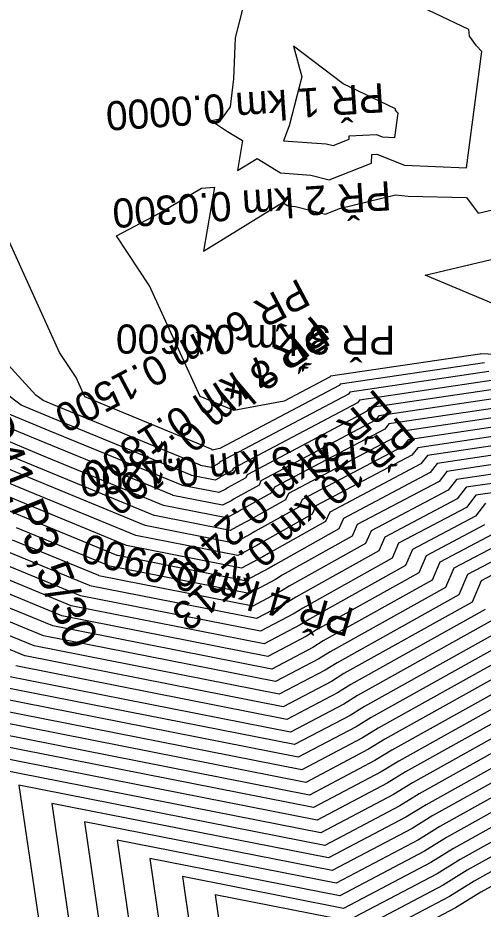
# Model space of a CAD drawing. Extents: x -549394 to -546608, y -1037055 to -1033629.
# Drawn here: x -547337.6 to -547192.8, y -1036070.9 to -1035793.8 of the extents above; entities that cross this region are included whole.
import ezdxf

# ---------------------------------------------------------------- set-up
doc = ezdxf.new("R2010")
doc.units = 0
for name, color, linetype in [('hlavni_vrst', 7, 'Continuous'), ('norm_vrst', 7, 'Continuous'), ('x_popis_pricne_rezy_C41', 7, 'Continuous'), ('x_popis_velky_C41', 7, 'Continuous')]:
    doc.layers.add(name, color=color, linetype=linetype)

msp = doc.modelspace()

# ---------------------------------------------------------------- linework, layer by layer
at = {"layer": 'hlavni_vrst'}
for p, q in [((-547251.82, -1035802.56), (-547249.25, -1035812.17)), ((-547236.37, -1035814.31), (-547251.82, -1035802.56)), ((-547249.25, -1035812.17), (-547253.15, -1035827.42)), ((-547220.11, -1035822.08), (-547236.37, -1035814.31)), ((-547220.26, -1035830.95), (-547219.26, -1035823.48)), ((-547220.05, -1035822.5), (-547220.11, -1035822.08)), ((-547219.61, -1035823.12), (-547220.05, -1035822.5)), ((-547219.26, -1035823.48), (-547219.61, -1035823.12)), ((-547253.15, -1035827.42), (-547254.99, -1035832)), ((-547254.99, -1035832), (-547241.63, -1035832.93)), ((-547239.49, -1035833.48), (-547234.56, -1035831.56)), ((-547234.56, -1035831.56), (-547234.51, -1035830.53)), ((-547234.51, -1035830.53), (-547226.01, -1035830.08)), ((-547226.01, -1035830.08), (-547224.23, -1035830.78)), ((-547224.23, -1035830.78), (-547220.26, -1035830.95)), ((-547241.63, -1035832.93), (-547239.49, -1035833.48)), ((-547332, -1035911.09), (-547360.95, -1035879.77)), ((-547191.02, -1035903.73), (-547234.27, -1035910.17)), ((-547329.73, -1035912.78), (-547332, -1035911.09)), ((-547325.32, -1035914.6), (-547329.73, -1035912.78)), ((-547234.76, -1035910.81), (-547274.88, -1035931.97)), ((-547234.27, -1035910.17), (-547234.76, -1035910.81)), ((-547280.8, -1035932.89), (-547325.32, -1035914.6)), ((-547184.08, -1035917.28), (-547219.2, -1035922.5)), ((-547331.66, -1035933.5), (-547363.96, -1035920.2)), ((-547219.2, -1035922.5), (-547220.63, -1035924.36)), ((-547220.63, -1035924.36), (-547253.44, -1035941.66)), ((-547275, -1035932.24), (-547276.65, -1035933.17)), ((-547274.88, -1035931.97), (-547275, -1035932.24)), ((-547177.14, -1035930.82), (-547204.14, -1035934.84)), ((-547295.17, -1035948.49), (-547331.66, -1035933.5)), ((-547280.76, -1035932.94), (-547280.8, -1035932.89)), ((-547277.43, -1035933.59), (-547280.76, -1035932.94)), ((-547276.81, -1035933.27), (-547277.43, -1035933.59)), ((-547276.65, -1035933.17), (-547276.81, -1035933.27)), ((-547204.14, -1035934.84), (-547206.51, -1035937.92)), ((-547206.51, -1035937.92), (-547231.99, -1035951.36)), ((-547253.44, -1035941.66), (-547254.29, -1035943.62)), ((-547254.29, -1035943.62), (-547265.99, -1035950.15)), ((-547295.14, -1035948.53), (-547295.17, -1035948.49)), ((-547271.55, -1035953.18), (-547295.14, -1035948.53)), ((-547267.14, -1035950.86), (-547271.55, -1035953.18)), ((-547265.99, -1035950.15), (-547267.14, -1035950.86)), ((-547231.99, -1035951.36), (-547233.57, -1035954.99)), ((-547192.38, -1035951.47), (-547210.55, -1035961.05)), ((-547309.54, -1035964.1), (-547338, -1035952.4)), ((-547233.57, -1035954.99), (-547255.34, -1035967.13)), ((-547210.55, -1035961.05), (-547212.86, -1035966.36)), ((-547309.51, -1035964.13), (-547309.54, -1035964.1)), ((-547265.67, -1035972.76), (-547309.51, -1035964.13)), ((-547255.34, -1035967.13), (-547257.47, -1035968.45)), ((-547212.86, -1035966.36), (-547244.68, -1035984.12)), ((-547257.47, -1035968.45), (-547265.67, -1035972.76)), ((-547323.91, -1035979.7), (-547344.34, -1035971.31)), ((-547192.14, -1035977.73), (-547234.02, -1036001.1)), ((-547323.89, -1035979.72), (-547323.91, -1035979.7)), ((-547259.78, -1035992.35), (-547323.89, -1035979.72)), ((-547244.68, -1035984.12), (-547247.8, -1035986.04)), ((-547247.8, -1035986.04), (-547259.78, -1035992.35)), ((-547171.43, -1035989.1), (-547223.36, -1036018.08)), ((-547253.9, -1036011.93), (-547338.27, -1035995.32)), ((-547234.02, -1036001.1), (-547238.12, -1036003.63)), ((-547238.12, -1036003.63), (-547253.9, -1036011.93)), ((-547161.94, -1036006.74), (-547212.7, -1036035.07)), ((-547248.01, -1036031.52), (-547352.65, -1036010.92)), ((-547223.36, -1036018.08), (-547228.45, -1036021.22)), ((-547228.45, -1036021.22), (-547248.01, -1036031.52)), ((-547337.27, -1036032.37), (-547329.59, -1036084.85)), ((-547242.13, -1036051.11), (-547337.27, -1036032.37)), ((-547212.7, -1036035.07), (-547218.78, -1036038.81)), ((-547218.78, -1036038.81), (-547242.13, -1036051.11)), ((-547177.7, -1036038.46), (-547202.05, -1036052.05)), ((-547202.05, -1036052.05), (-547209.1, -1036056.41)), ((-547209.1, -1036056.41), (-547236.25, -1036070.69)), ((-547286.38, -1036060.82), (-547282.33, -1036088.47)), ((-547236.25, -1036070.69), (-547286.38, -1036060.82))]:
    msp.add_line(p, q, dxfattribs=at)
at = {"layer": 'norm_vrst'}
for p, q in [((-547197.3, -1035797.44), (-547264.33, -1035765.41)), ((-547266.72, -1035787.33), (-547269.97, -1035799.98)), ((-547197.02, -1035799.47), (-547197.3, -1035797.44)), ((-547269.97, -1035799.98), (-547270.5, -1035812.79)), ((-547194.88, -1035802.45), (-547197.02, -1035799.47)), ((-547198.02, -1035840.41), (-547193.19, -1035804.21)), ((-547193.19, -1035804.21), (-547194.88, -1035802.45)), ((-547270.5, -1035812.79), (-547271.59, -1035821.51)), ((-547271.59, -1035821.51), (-547274.2, -1035825.16)), ((-547274.2, -1035825.16), (-547277.37, -1035825.83)), ((-547277.37, -1035825.83), (-547272.34, -1035829.09)), ((-547272.34, -1035829.09), (-547267.66, -1035831.93)), ((-547267.66, -1035831.93), (-547269.28, -1035841.28)), ((-547269.28, -1035841.28), (-547263.18, -1035837.53)), ((-547263.18, -1035837.53), (-547255.86, -1035842.02)), ((-547227.55, -1035839.03), (-547227.44, -1035836.28)), ((-547227.44, -1035836.28), (-547225.9, -1035836.2)), ((-547225.9, -1035836.2), (-547217.26, -1035839.59)), ((-547240.7, -1035844.14), (-547227.55, -1035839.03)), ((-547217.26, -1035839.59), (-547198.02, -1035840.41)), ((-547255.86, -1035842.02), (-547246.41, -1035842.68)), ((-547246.41, -1035842.68), (-547240.7, -1035844.14)), ((-547293.7, -1035854.68), (-547280.51, -1035846.71)), ((-547280.51, -1035846.71), (-547276.4, -1035846.42)), ((-547276.4, -1035846.42), (-547279.84, -1035866.32)), ((-547237.47, -1035853.07), (-547220.1, -1035848.82)), ((-547220.1, -1035848.82), (-547216.13, -1035849.24)), ((-547279.84, -1035866.32), (-547255.25, -1035851.18)), ((-547255.25, -1035851.18), (-547253.48, -1035852.27)), ((-547216.13, -1035849.24), (-547198, -1035849.68)), ((-547198, -1035849.68), (-547194.35, -1035854.53)), ((-547194.35, -1035854.53), (-547180.63, -1035851.28)), ((-547306.97, -1035861.55), (-547293.7, -1035854.68)), ((-547253.48, -1035852.27), (-547251.19, -1035852.43)), ((-547251.19, -1035852.43), (-547241.91, -1035854.8)), ((-547241.91, -1035854.8), (-547237.47, -1035853.07)), ((-547324.65, -1035897.88), (-547341.16, -1035861.46)), ((-547296.68, -1035877.13), (-547306.97, -1035861.55)), ((-547210.83, -1035873.81), (-547170.49, -1035864.25)), ((-547183, -1035885.49), (-547210.83, -1035873.81)), ((-547280.88, -1035911.53), (-547296.68, -1035877.13)), ((-547319.52, -1035905.63), (-547324.65, -1035897.88)), ((-547193.8, -1035898.32), (-547240.29, -1035905.23)), ((-547193.61, -1035898.22), (-547193.8, -1035898.32)), ((-547158.47, -1035899.73), (-547193.61, -1035898.22)), ((-547192.41, -1035901.02), (-547237.28, -1035907.7)), ((-547316.78, -1035911.6), (-547319.52, -1035905.63)), ((-547240.41, -1035905.39), (-547254.79, -1035912.97)), ((-547240.29, -1035905.23), (-547240.41, -1035905.39)), ((-547189.63, -1035906.44), (-547231.25, -1035912.63)), ((-547237.58, -1035908.1), (-547274.8, -1035927.72)), ((-547237.28, -1035907.7), (-547237.58, -1035908.1)), ((-547188.25, -1035909.15), (-547228.24, -1035915.1)), ((-547336.57, -1035914.27), (-547341.71, -1035910.43)), ((-547277.18, -1035928.05), (-547316.78, -1035911.6)), ((-547270.39, -1035915.88), (-547280.88, -1035911.53)), ((-547231.25, -1035912.63), (-547231.93, -1035913.52)), ((-547186.86, -1035911.86), (-547225.23, -1035917.57)), ((-547326.59, -1035918.38), (-547336.57, -1035914.27)), ((-547231.93, -1035913.52), (-547270.59, -1035933.91)), ((-547254.79, -1035912.97), (-547270.39, -1035915.91)), ((-547228.24, -1035915.1), (-547229.11, -1035916.23)), ((-547185.47, -1035914.57), (-547222.21, -1035920.04)), ((-547329.13, -1035925.94), (-547350.26, -1035917.23)), ((-547327.86, -1035922.16), (-547343.42, -1035915.75)), ((-547283.67, -1035936.01), (-547326.59, -1035918.38)), ((-547270.39, -1035915.91), (-547270.39, -1035915.88)), ((-547229.11, -1035916.23), (-547266.3, -1035935.85)), ((-547225.23, -1035917.57), (-547226.28, -1035918.94)), ((-547330.39, -1035929.72), (-547357.11, -1035918.72)), ((-547226.28, -1035918.94), (-547262.02, -1035937.79)), ((-547222.21, -1035920.04), (-547223.46, -1035921.65)), ((-547182.7, -1035919.99), (-547216.19, -1035924.97)), ((-547334.2, -1035941.06), (-547377.65, -1035923.17)), ((-547332.93, -1035937.28), (-547370.8, -1035921.69)), ((-547286.55, -1035939.13), (-547327.86, -1035922.16)), ((-547223.46, -1035921.65), (-547257.73, -1035939.72)), ((-547181.31, -1035922.69), (-547213.17, -1035927.44)), ((-547336.73, -1035948.62), (-547391.34, -1035926.14)), ((-547335.47, -1035944.84), (-547384.49, -1035924.65)), ((-547289.42, -1035942.25), (-547329.13, -1035925.94)), ((-547216.19, -1035924.97), (-547217.81, -1035927.07)), ((-547179.92, -1035925.4), (-547210.16, -1035929.9)), ((-547274.8, -1035927.72), (-547277.18, -1035928.17)), ((-547277.18, -1035928.17), (-547277.18, -1035928.05)), ((-547217.81, -1035927.07), (-547249.15, -1035943.6)), ((-547213.17, -1035927.44), (-547214.98, -1035929.78)), ((-547178.53, -1035928.11), (-547207.15, -1035932.37)), ((-547292.29, -1035945.37), (-547330.39, -1035929.72)), ((-547214.98, -1035929.78), (-547244.86, -1035945.54)), ((-547210.16, -1035929.9), (-547212.16, -1035932.49)), ((-547270.86, -1035934.52), (-547274.52, -1035936.56)), ((-547270.59, -1035933.91), (-547270.86, -1035934.52)), ((-547212.16, -1035932.49), (-547240.57, -1035947.48)), ((-547207.15, -1035932.37), (-547209.33, -1035935.21)), ((-547175.76, -1035933.53), (-547201.12, -1035937.3)), ((-547298.04, -1035951.61), (-547332.93, -1035937.28)), ((-547283.63, -1035936.06), (-547283.67, -1035936.01)), ((-547276.26, -1035937.51), (-547283.63, -1035936.06)), ((-547274.88, -1035936.78), (-547276.26, -1035937.51)), ((-547274.52, -1035936.56), (-547274.88, -1035936.78)), ((-547266.72, -1035936.79), (-547272.39, -1035939.96)), ((-547266.3, -1035935.85), (-547266.72, -1035936.79)), ((-547262.02, -1035937.79), (-547262.57, -1035939.07)), ((-547209.33, -1035935.21), (-547236.28, -1035949.42)), ((-547201.12, -1035937.3), (-547203.68, -1035940.63)), ((-547174.37, -1035936.24), (-547198.11, -1035939.77)), ((-547286.51, -1035939.18), (-547286.55, -1035939.13)), ((-547275.08, -1035941.43), (-547286.51, -1035939.18)), ((-547272.94, -1035940.3), (-547275.08, -1035941.43)), ((-547272.39, -1035939.96), (-547272.94, -1035940.3)), ((-547262.57, -1035939.07), (-547270.26, -1035943.36)), ((-547257.73, -1035939.72), (-547258.43, -1035941.34)), ((-547198.11, -1035939.77), (-547200.86, -1035943.34)), ((-547172.98, -1035938.95), (-547195.1, -1035942.24)), ((-547300.92, -1035954.73), (-547334.2, -1035941.06)), ((-547289.38, -1035942.3), (-547289.42, -1035942.25)), ((-547273.9, -1035945.34), (-547289.38, -1035942.3)), ((-547270.26, -1035943.36), (-547271.01, -1035943.82)), ((-547258.43, -1035941.34), (-547268.13, -1035946.75)), ((-547203.68, -1035940.63), (-547227.7, -1035953.3)), ((-547200.86, -1035943.34), (-547223.41, -1035955.23)), ((-547195.1, -1035942.24), (-547198.03, -1035946.05)), ((-547303.79, -1035957.86), (-547335.47, -1035944.84)), ((-547292.26, -1035945.41), (-547292.29, -1035945.37)), ((-547272.73, -1035949.26), (-547292.26, -1035945.41)), ((-547271.01, -1035943.82), (-547273.9, -1035945.34)), ((-547250.14, -1035945.89), (-547263.86, -1035953.55)), ((-547249.15, -1035943.6), (-547250.14, -1035945.89)), ((-547244.86, -1035945.54), (-547246, -1035948.16)), ((-547198.03, -1035946.05), (-547219.13, -1035957.17)), ((-547192.08, -1035944.7), (-547195.21, -1035948.76)), ((-547306.67, -1035960.98), (-547336.73, -1035948.62)), ((-547269.08, -1035947.34), (-547272.73, -1035949.26)), ((-547268.13, -1035946.75), (-547269.08, -1035947.34)), ((-547246, -1035948.16), (-547261.73, -1035956.94)), ((-547240.57, -1035947.48), (-547241.86, -1035950.44)), ((-547195.21, -1035948.76), (-547214.84, -1035959.11)), ((-547298.01, -1035951.65), (-547298.04, -1035951.61)), ((-547270.37, -1035957.09), (-547298.01, -1035951.65)), ((-547241.86, -1035950.44), (-547259.6, -1035960.34)), ((-547236.28, -1035949.42), (-547237.71, -1035952.71)), ((-547265.21, -1035954.37), (-547270.37, -1035957.09)), ((-547263.86, -1035953.55), (-547265.21, -1035954.37)), ((-547237.71, -1035952.71), (-547257.47, -1035963.74)), ((-547227.7, -1035953.3), (-547229.43, -1035957.26)), ((-547189.56, -1035954.18), (-547206.26, -1035962.99)), ((-547312.41, -1035967.22), (-547339.27, -1035956.19)), ((-547300.89, -1035954.77), (-547300.92, -1035954.73)), ((-547269.2, -1035961.01), (-547300.89, -1035954.77)), ((-547261.73, -1035956.94), (-547263.27, -1035957.89)), ((-547223.41, -1035955.23), (-547225.29, -1035959.54)), ((-547219.13, -1035957.17), (-547221.14, -1035961.81)), ((-547186.73, -1035956.89), (-547201.97, -1035964.93)), ((-547315.29, -1035970.34), (-547340.54, -1035959.97)), ((-547303.76, -1035957.89), (-547303.79, -1035957.86)), ((-547268.02, -1035964.93), (-547303.76, -1035957.89)), ((-547263.27, -1035957.89), (-547269.2, -1035961.01)), ((-547229.43, -1035957.26), (-547253.2, -1035970.53)), ((-547225.29, -1035959.54), (-547251.07, -1035973.93)), ((-547214.84, -1035959.11), (-547217, -1035964.08)), ((-547183.91, -1035959.6), (-547197.68, -1035966.87)), ((-547306.64, -1035961.01), (-547306.67, -1035960.98)), ((-547266.84, -1035968.85), (-547306.64, -1035961.01)), ((-547261.34, -1035961.41), (-547268.02, -1035964.93)), ((-547259.6, -1035960.34), (-547261.34, -1035961.41)), ((-547221.14, -1035961.81), (-547248.94, -1035977.32)), ((-547181.08, -1035962.31), (-547193.39, -1035968.81)), ((-547318.16, -1035973.46), (-547341.81, -1035963.75)), ((-547259.4, -1035964.93), (-547266.84, -1035968.85)), ((-547257.47, -1035963.74), (-547259.4, -1035964.93)), ((-547217, -1035964.08), (-547246.81, -1035980.72)), ((-547206.26, -1035962.99), (-547208.71, -1035968.63)), ((-547201.97, -1035964.93), (-547204.57, -1035970.91)), ((-547321.04, -1035976.58), (-547343.07, -1035967.53)), ((-547312.39, -1035967.25), (-547312.41, -1035967.22)), ((-547264.49, -1035976.68), (-547312.39, -1035967.25)), ((-547197.68, -1035966.87), (-547200.43, -1035973.18)), ((-547315.27, -1035970.37), (-547315.29, -1035970.34)), ((-547263.31, -1035980.6), (-547315.27, -1035970.37)), ((-547253.2, -1035970.53), (-547255.53, -1035971.97)), ((-547208.71, -1035968.63), (-547242.55, -1035987.51)), ((-547204.57, -1035970.91), (-547240.42, -1035990.91)), ((-547193.39, -1035968.81), (-547196.28, -1035975.46)), ((-547318.14, -1035973.49), (-547318.16, -1035973.46)), ((-547262.14, -1035984.51), (-547318.14, -1035973.49)), ((-547255.53, -1035971.97), (-547264.49, -1035976.68)), ((-547200.43, -1035973.18), (-547238.28, -1035994.31)), ((-547326.78, -1035982.82), (-547345.61, -1035975.09)), ((-547321.02, -1035976.61), (-547321.04, -1035976.58)), ((-547260.96, -1035988.43), (-547321.02, -1035976.61)), ((-547253.6, -1035975.48), (-547263.31, -1035980.6)), ((-547251.07, -1035973.93), (-547253.6, -1035975.48)), ((-547196.28, -1035975.46), (-547236.15, -1035997.7)), ((-547329.66, -1035985.94), (-547346.88, -1035978.87)), ((-547251.66, -1035979), (-547262.14, -1035984.51)), ((-547248.94, -1035977.32), (-547251.66, -1035979)), ((-547246.81, -1035980.72), (-547249.73, -1035982.52)), ((-547188, -1035980), (-547231.89, -1036004.5)), ((-547332.53, -1035989.06), (-547348.15, -1035982.65)), ((-547326.77, -1035982.84), (-547326.78, -1035982.82)), ((-547258.61, -1035996.27), (-547326.77, -1035982.84)), ((-547249.73, -1035982.52), (-547260.96, -1035988.43)), ((-547183.85, -1035982.28), (-547229.76, -1036007.89)), ((-547179.71, -1035984.55), (-547227.63, -1036011.29)), ((-547335.41, -1035992.19), (-547349.41, -1035986.43)), ((-547329.64, -1035985.96), (-547329.66, -1035985.94)), ((-547257.43, -1036000.18), (-547329.64, -1035985.96)), ((-547242.55, -1035987.51), (-547245.86, -1035989.56)), ((-547175.57, -1035986.83), (-547225.49, -1036014.69)), ((-547332.52, -1035989.08), (-547332.53, -1035989.06)), ((-547256.25, -1036004.1), (-547332.52, -1035989.08)), ((-547245.86, -1035989.56), (-547258.61, -1035996.27)), ((-547335.39, -1035992.2), (-547335.41, -1035992.19)), ((-547255.07, -1036008.02), (-547335.39, -1035992.2)), ((-547243.93, -1035993.08), (-547257.43, -1036000.18)), ((-547240.42, -1035990.91), (-547243.93, -1035993.08)), ((-547167.28, -1035991.38), (-547221.23, -1036021.48)), ((-547238.28, -1035994.31), (-547241.99, -1035996.59)), ((-547163.14, -1035993.65), (-547219.1, -1036024.88)), ((-547159, -1035995.92), (-547216.97, -1036028.27)), ((-547252.72, -1036015.85), (-547341.15, -1035998.44)), ((-547241.99, -1035996.59), (-547256.25, -1036004.1)), ((-547236.15, -1035997.7), (-547240.06, -1036000.11)), ((-547251.54, -1036019.77), (-547344.02, -1036001.56)), ((-547240.06, -1036000.11), (-547255.07, -1036008.02)), ((-547158.79, -1036000.4), (-547214.84, -1036031.67)), ((-547250.37, -1036023.69), (-547346.9, -1036004.68)), ((-547231.89, -1036004.5), (-547236.19, -1036007.15)), ((-547249.19, -1036027.6), (-547349.77, -1036007.8)), ((-547236.19, -1036007.15), (-547252.72, -1036015.85)), ((-547229.76, -1036007.89), (-547234.25, -1036010.67)), ((-547234.25, -1036010.67), (-547251.54, -1036019.77)), ((-547227.63, -1036011.29), (-547232.32, -1036014.19)), ((-547246.84, -1036035.44), (-547355.52, -1036014.04)), ((-547232.32, -1036014.19), (-547250.37, -1036023.69)), ((-547225.49, -1036014.69), (-547230.38, -1036017.7)), ((-547165.09, -1036013.08), (-547210.57, -1036038.46)), ((-547245.66, -1036039.35), (-547358.4, -1036017.15)), ((-547230.38, -1036017.7), (-547249.19, -1036027.6)), ((-547168.24, -1036019.43), (-547208.44, -1036041.86)), ((-547244.48, -1036043.27), (-547357.62, -1036020.99)), ((-547221.23, -1036021.48), (-547226.52, -1036024.74)), ((-547226.52, -1036024.74), (-547246.84, -1036035.44)), ((-547219.1, -1036024.88), (-547224.58, -1036028.26)), ((-547171.39, -1036025.77), (-547206.31, -1036045.26)), ((-547243.31, -1036047.19), (-547347.44, -1036026.68)), ((-547224.58, -1036028.26), (-547245.66, -1036039.35)), ((-547216.97, -1036028.27), (-547222.65, -1036031.78)), ((-547222.65, -1036031.78), (-547244.48, -1036043.27)), ((-547214.84, -1036031.67), (-547220.71, -1036035.3)), ((-547174.54, -1036032.12), (-547204.18, -1036048.65)), ((-547220.71, -1036035.3), (-547243.31, -1036047.19)), ((-547327.09, -1036038.06), (-547320.14, -1036085.57)), ((-547240.95, -1036055.02), (-547327.09, -1036038.06)), ((-547210.57, -1036038.46), (-547216.84, -1036042.33)), ((-547216.84, -1036042.33), (-547240.95, -1036055.02)), ((-547208.44, -1036041.86), (-547214.91, -1036045.85)), ((-547316.91, -1036043.75), (-547310.69, -1036086.3)), ((-547239.78, -1036058.94), (-547316.91, -1036043.75)), ((-547214.91, -1036045.85), (-547239.78, -1036058.94)), ((-547206.31, -1036045.26), (-547212.97, -1036049.37)), ((-547180.85, -1036044.81), (-547199.92, -1036055.45)), ((-547204.18, -1036048.65), (-547211.04, -1036052.89)), ((-547306.73, -1036049.44), (-547301.23, -1036087.02)), ((-547238.6, -1036062.86), (-547306.73, -1036049.44)), ((-547212.97, -1036049.37), (-547238.6, -1036062.86)), ((-547184, -1036051.15), (-547197.78, -1036058.84)), ((-547211.04, -1036052.89), (-547237.42, -1036066.77)), ((-547296.56, -1036055.13), (-547291.78, -1036087.75)), ((-547237.42, -1036066.77), (-547296.56, -1036055.13)), ((-547199.92, -1036055.45), (-547207.17, -1036059.92)), ((-547197.78, -1036058.84), (-547205.23, -1036063.44)), ((-547187.15, -1036057.5), (-547195.65, -1036062.24)), ((-547207.17, -1036059.92), (-547235.07, -1036074.61)), ((-547195.65, -1036062.24), (-547203.3, -1036066.96)), ((-547205.23, -1036063.44), (-547233.89, -1036078.53)), ((-547190.3, -1036063.84), (-547193.52, -1036065.64)), ((-547276.2, -1036066.51), (-547272.88, -1036089.2)), ((-547235.07, -1036074.61), (-547276.2, -1036066.51)), ((-547203.3, -1036066.96), (-547232.71, -1036082.44)), ((-547193.52, -1036065.64), (-547201.37, -1036070.48)), ((-547201.37, -1036070.48), (-547231.54, -1036086.36))]:
    msp.add_line(p, q, dxfattribs=at)

# ---------------------------------------------------------------- texts
at = {"layer": 'x_popis_pricne_rezy_C41'}
for s, rotation, p in [('PŘ 1 km 0.0000', 183.8301, (-547223.79, -1035814.07)), ('PŘ 2 km 0.0300', 183.6859, (-547221.72, -1035844.55)), ('PŘ 6 km 0.1500', 207.8077, (-547250.12, -1035874.63)), ('PŘ 7 km 0.1800', 212.0448, (-547244.53, -1035887.37)), ('PŘ 8 km 0.2100', 220.3973, (-547245.79, -1035885.98)), ('PŘ 3 km 0.0600', 179.756, (-547220.19, -1035889.49)), ('PŘ 9 km 0.2400', 220.3973, (-547226.35, -1035908.83)), ('PŘ 10 km 0.2513', 220.3973, (-547219.05, -1035917.4)), ('PŘ 5 km 0.1200', 185.8991, (-547232.32, -1035924.89)), ('PŘ 4 km 0.0900', 164.1726, (-547232.46, -1035977.66))]:
    msp.add_text(s, height=9.0627, rotation=rotation, dxfattribs=at).set_placement(p)
at = {"layer": 'x_popis_velky_C41'}
msp.add_text('C41,P3,5/30', height=10.5, rotation=291.7026, dxfattribs=at).set_placement((-547350.98, -1035918.38))

doc.saveas('drawing.dxf')
